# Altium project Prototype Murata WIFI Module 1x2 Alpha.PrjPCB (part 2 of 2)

## Sheet FPGA Config.SchDoc: FPGA Configuration
size B; Date: 10/29/2013; DrawnBy: David McCoy; Engineer: David McCoy (Cospan Design); DocumentNumber: 4; Revision: A; SheetNumber: 4; SheetTotal: 11
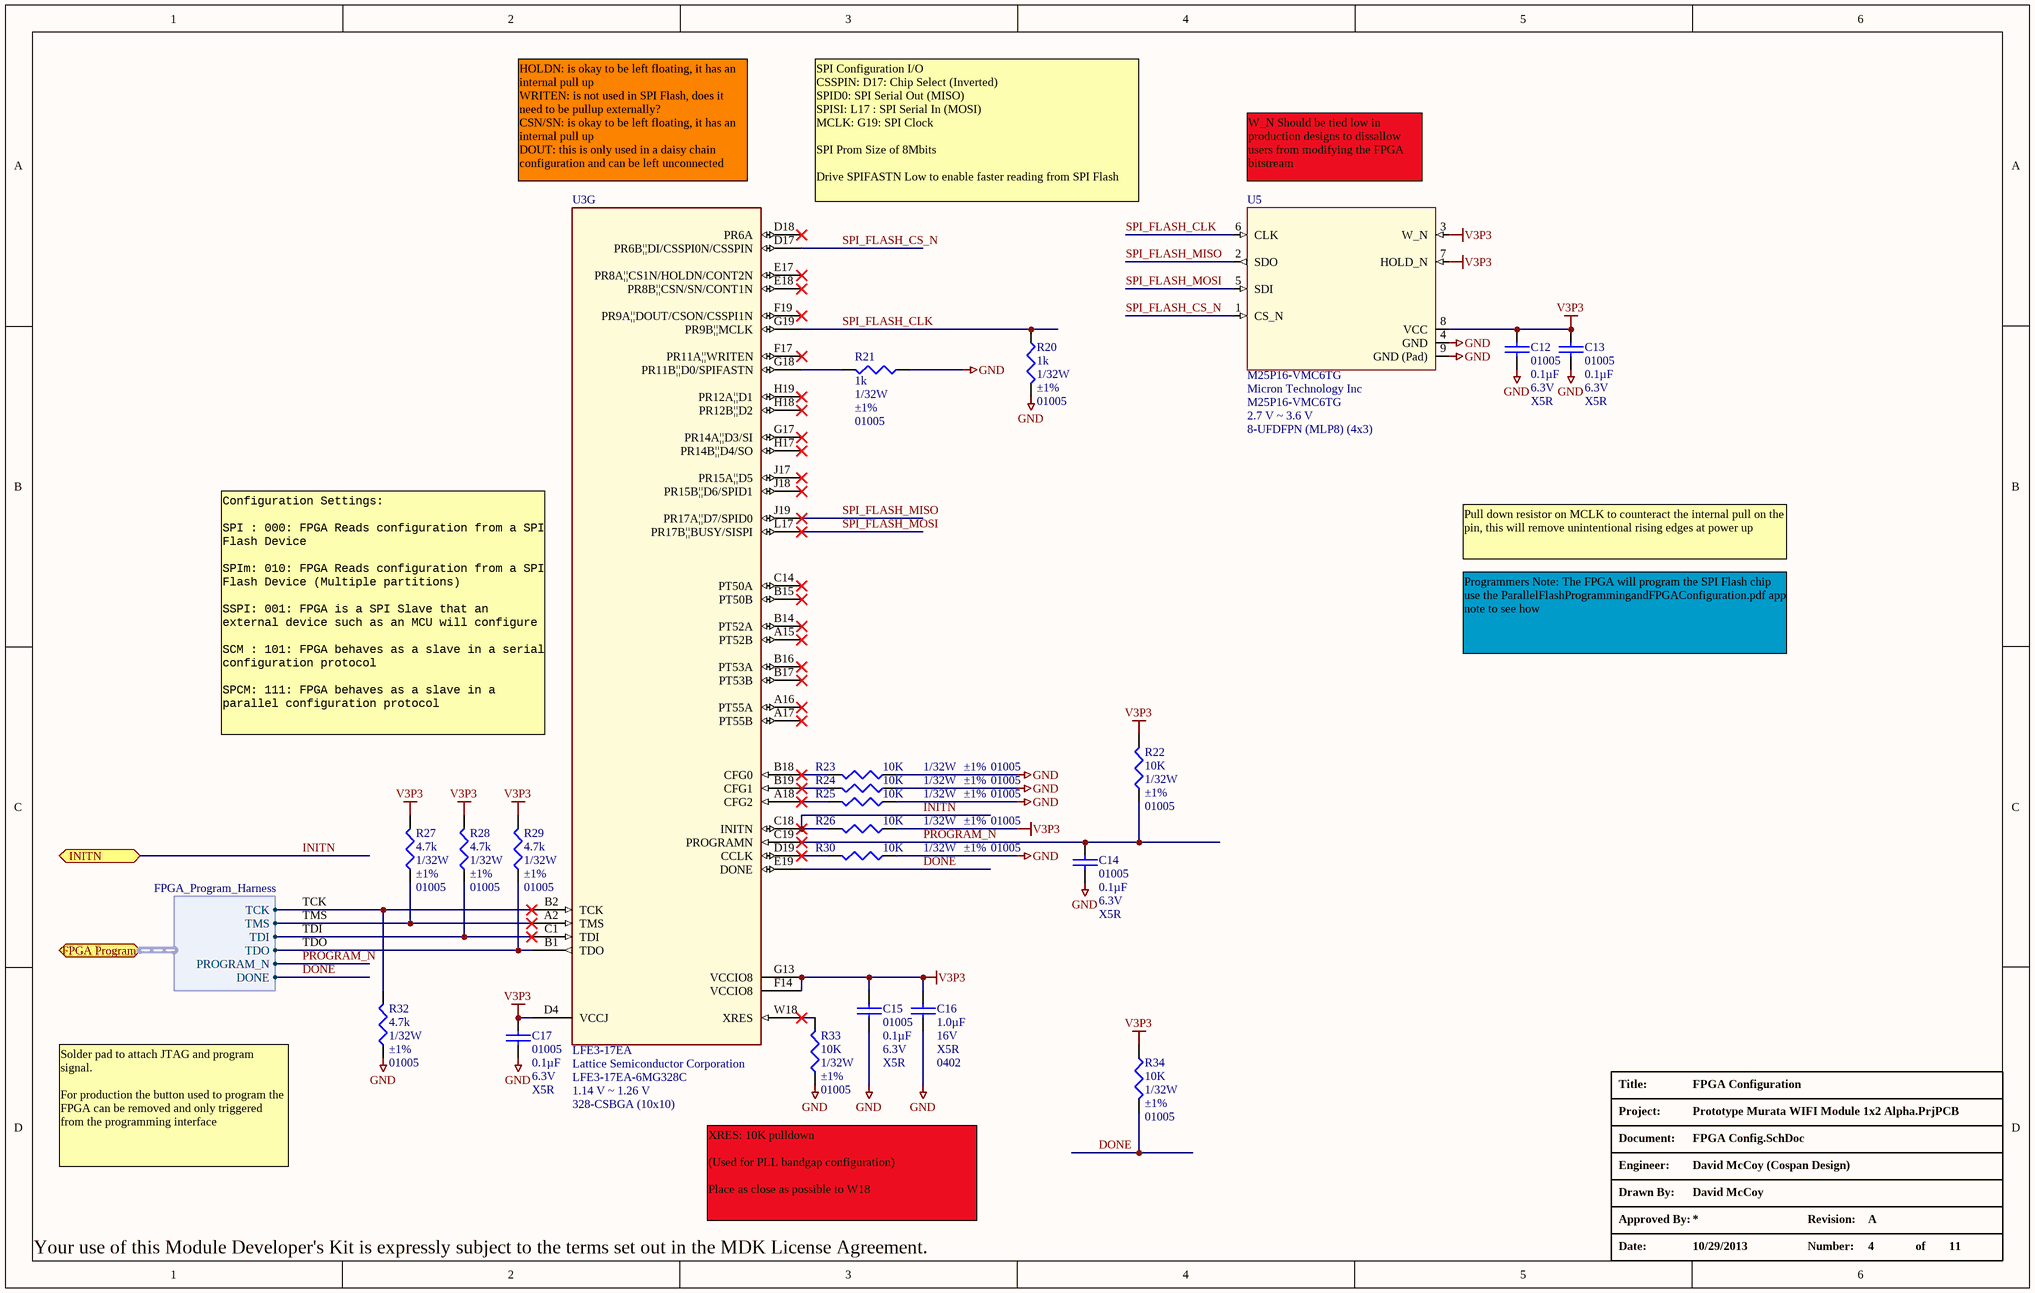
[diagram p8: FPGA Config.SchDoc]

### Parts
C12  Package / Case: 01005  Capacitance: 0.1µF  Voltage - Rated: 6.3V  Temperature Coefficient: X5R  [C_01005]  (hidden comment: 0.1uF)
C13  Package / Case: 01005  Capacitance: 0.1µF  Voltage - Rated: 6.3V  Temperature Coefficient: X5R  [C_01005]  (hidden comment: 0.1uF)
C14  Package / Case: 01005  Capacitance: 0.1µF  Voltage - Rated: 6.3V  Temperature Coefficient: X5R  [C_01005]  (hidden comment: 0.1uF)
C15  Package / Case: 01005  Capacitance: 0.1µF  Voltage - Rated: 6.3V  Temperature Coefficient: X5R  [C_01005]  (hidden comment: 0.1uF)
C16  Capacitance: 1.0µF  Voltage - Rated: 16V  Temperature Coefficient: X5R  Package / Case: 0402  [C_ERA-0402]  (hidden comment: 1.0uF)
C17  Package / Case: 01005  Capacitance: 0.1µF  Voltage - Rated: 6.3V  Temperature Coefficient: X5R  [C_01005]  (hidden comment: 0.1uF)
R20  Power (Watts): 1/32W  Tolerance: ±1%  Case: 01005  [R_01005]  (hidden comment: 1k)
R21  Power (Watts): 1/32W  Tolerance: ±1%  Case: 01005  [R_01005]  (hidden comment: 1k)
R22  Power (Watts): 1/32W  Tolerance: ±1%  Case: 01005  [R_01005]  (hidden comment: 10K)
R23  Power (Watts): 1/32W  Tolerance: ±1%  Case: 01005  [R_01005]  (hidden comment: 10K)
R24  Power (Watts): 1/32W  Tolerance: ±1%  Case: 01005  [R_01005]  (hidden comment: 10K)
R25  Power (Watts): 1/32W  Tolerance: ±1%  Case: 01005  [R_01005]  (hidden comment: 10K)
R26  Power (Watts): 1/32W  Tolerance: ±1%  Case: 01005  [R_01005]  (hidden comment: 10K)
R27  Power (Watts): 1/32W  Tolerance: ±1%  Case: 01005  [R_01005]  (hidden comment: 4.7k)
R28  Power (Watts): 1/32W  Tolerance: ±1%  Case: 01005  [R_01005]  (hidden comment: 4.7k)
R29  Power (Watts): 1/32W  Tolerance: ±1%  Case: 01005  [R_01005]  (hidden comment: 4.7k)
R30  Power (Watts): 1/32W  Tolerance: ±1%  Case: 01005  [R_01005]  (hidden comment: 10K)
R32  Power (Watts): 1/32W  Tolerance: ±1%  Case: 01005  [R_01005]  (hidden comment: 4.7k)
R33  Power (Watts): 1/32W  Tolerance: ±1%  Case: 01005  [R_01005]  (hidden comment: 10K)
R34  Power (Watts): 1/32W  Tolerance: ±1%  Case: 01005  [R_01005]  (hidden comment: 10K)
U3  LFE3-17EA  Manufacturer: Lattice Semiconductor Corporation  Manufacturer Part Number: LFE3-17EA-6MG328C  Voltage - Supply: 1.14 V ~ 1.26 V  Supplier Device Package: 328-CSBGA (10x10)  [BGA328C50P19X19_1000X1000X150]  (part G of 10)
U5  M25P16-VMC6TG  Manufacturer: Micron Technology Inc  Voltage - Supply: 2.7 V ~ 3.6 V  Supplier Device Package: 8-UFDFPN (MLP8) (4x3)  [UFDFN8]

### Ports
FPGA Program (harness FPGA_Program_Harness), INITN

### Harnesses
FPGA_Program_Harness: TCK, TMS, TDI, TDO, PROGRAM_N, DONE

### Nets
GND: C12.2 C13.2 C14.2 C15.2 C16.1 C17.2 R20.1 R21.2 R23.2 R24.2 R25.2 R30.2 R32.2 R33.2 U5.4(GND) U5.9(GND_(Pad))
V3P3: C12.1 C13.1 C15.1 C16.2 C17.1 R22.1 R26.2 R27.1 R28.1 R29.1 R34.2 U3.D4(VCCJ) U3.F14(VCCIO8) U3.G13(VCCIO8) U5.3(W_N) U5.7(HOLD_N) U5.8(VCC)
DONE: R34.1 U3.E19(DONE) ; port FPGA Program.DONE
INITN: R26.1 U3.C18(INITN) ; port INITN
PROGRAM_N: C14.1 R22.2 U3.C19(PROGRAMN) ; port FPGA Program.PROGRAM_N
SPI_FLASH_CLK: R20.2 U3.G19(PR9B¦¦MCLK) U5.6(CLK)
SPI_FLASH_CS_N: U3.D17(PR6B¦¦DI/CSSPI0N/CSSPIN) U5.1(CS_N)
SPI_FLASH_MISO: U3.J19(PR17A¦¦D7/SPID0) U5.2(SDO)
SPI_FLASH_MOSI: U3.L17(PR17B¦¦BUSY/SISPI) U5.5(SDI)
TCK: R32.1 U3.B2(TCK) ; port FPGA Program.TCK
TDI: R28.2 U3.C1(TDI) ; port FPGA Program.TDI
TDO: R29.2 U3.B1(TDO) ; port FPGA Program.TDO
TMS: R27.2 U3.A2(TMS) ; port FPGA Program.TMS
NetR21_1: R21.1 U3.G18(PR11B¦¦D0/SPIFASTN)
NetR23_1: R23.1 U3.B18(CFG0)
NetR24_1: R24.1 U3.B19(CFG1)
NetR25_1: R25.1 U3.A18(CFG2)
NetR30_1: R30.1 U3.D19(CCLK)
NetR33_1: R33.1 U3.W18(XRES)

Not connected (* = marked no-connect by the designer): U3 A15(PT52B)* A16(PT55A)* A17(PT55B)* B14(PT52A)* B15(PT50B)* B16(PT53A)* B17(PT53B)* C14(PT50A)* D18(PR6A)* E17(PR8A¦¦CS1N/HOLDN/CONT2N)* E18(PR8B¦¦CSN/SN/CONT1N)* F17(PR11A¦¦WRITEN)* F19(PR9A¦¦DOUT/CSON/CSSPI1N)* G17(PR14A¦¦D3/SI)* H17(PR14B¦¦D4/SO)* H18(PR12B¦¦D2)* H19(PR12A¦¦D1)* J17(PR15A¦¦D5)* J18(PR15B¦¦D6/SPID1)*

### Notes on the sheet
- HOLDN: is okay to be left floating, it has an internal pull up
  WRITEN: is not used in SPI Flash, does it need to be pullup externally?
  CSN/SN: is okay to be left floating, it has an internal pull up
  DOUT: this is only used in a daisy chain configuration and can be left unconnected
- SPI Configuration I/O
  CSSPIN: D17: Chip Select (Inverted)
  SPID0: SPI Serial Out (MISO)
  SPISI: L17 : SPI Serial In (MOSI)
  MCLK: G19: SPI Clock
  SPI Prom Size of 8Mbits
  Drive SPIFASTN Low to enable faster reading from SPI Flash
- W_N Should be tied low in production designs to dissallow users from modifying the FPGA bitstream
- Pull down resistor on MCLK to counteract the internal pull on the pin, this will remove unintentional rising edges at power up
- Programmers Note: The FPGA will program the SPI Flash chip use the ParallelFlashProgrammingandFPGAConfiguration.pdf app note to see how
- (near U3) Configuration Settings:
  SPI : 000: FPGA Reads configuration from a SPI Flash Device
  SPIm: 010: FPGA Reads configuration from a SPI Flash Device (Multiple partitions)
  SSPI: 001: FPGA is a SPI Slave that an external device such as an MCU will configure
  SCM : 101: FPGA behaves as a slave in a serial configuration protocol
  SPCM: 111: FPGA behaves as a slave in a parallel configuration protocol
- Solder pad to attach JTAG and program signal.
  For production the button used to program the FPGA can be removed and only triggered from the programming interface
- XRES: 10K pulldown
  (Used for PLL bandgap configuration)
  Place as close as possible to W18

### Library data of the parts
C12-C15 C17 = C_01005_0.1uF: CAP CER 0.1UF 6.3V 20% X5R 01005; Manufacturer: TDK Corporation; Manufacturer Part Number: C0402X5R0J104M020BC
C16 = C_0402_1.0UF_16V: CAP CER 1.0UF 16V X5R 0402; Manufacturer: TDK Corporation; Manufacturer Part Number: C1005X5R1C105K; Tolerance: ±10%
R20 R21 = R_01005_1k: RES 1K OHM 1/32W 1% 01005 SM; Manufacturer: Panasonic Electronic Components; Manufacturer Part Number: ERJ-XGNF1001Y; Temperature Coefficient: ±200ppm/°C
R22-R26 R30 R33 R34 = R_01005_10K: RES 10K OHM 1/32W 1% 01005; Manufacturer: Samsung Electro-Mechanics America, Inc; Manufacturer Part Number: RC0402F103CS; Temperature Coefficient: ±250ppm/°C
R27-R29 R32 = R_01005_4.7k: RES 4.7K OHM 1/32W 1% 01005 SMD; Manufacturer: Yageo; Manufacturer Part Number: RC0100FR-074K7L; Temperature Coefficient: ±250ppm/°C
U3 = U_LFE3-17EA-MG328: IC FPGA 17KLUTS 116I/O 328-BGA; SPLIT_INST: TRUE; SWAP_INFO: (S1+S2+S3+S4+S5+S6+S7+S8+S9+S10); Number of LABs/CLBs: 2125; Number of Logic Elements/Cells: 17000; Total RAM Bits: 716800; Number of I /O: 116
U5 = U_M25P16-VMC6TG: IC FLASH 16MBIT 75MHZ 8UFDFPN; Memory Type: FLASH - NOR; Memory Size: 16M (2M x 8); Interface: SPI Serial

## Sheet Power.SchDoc: Power
size B; Date: 10/29/2013; DrawnBy: David McCoy; Engineer: David McCoy (Cospan Design); DocumentNumber: 11; Revision: A; SheetNumber: 11; SheetTotal: 11
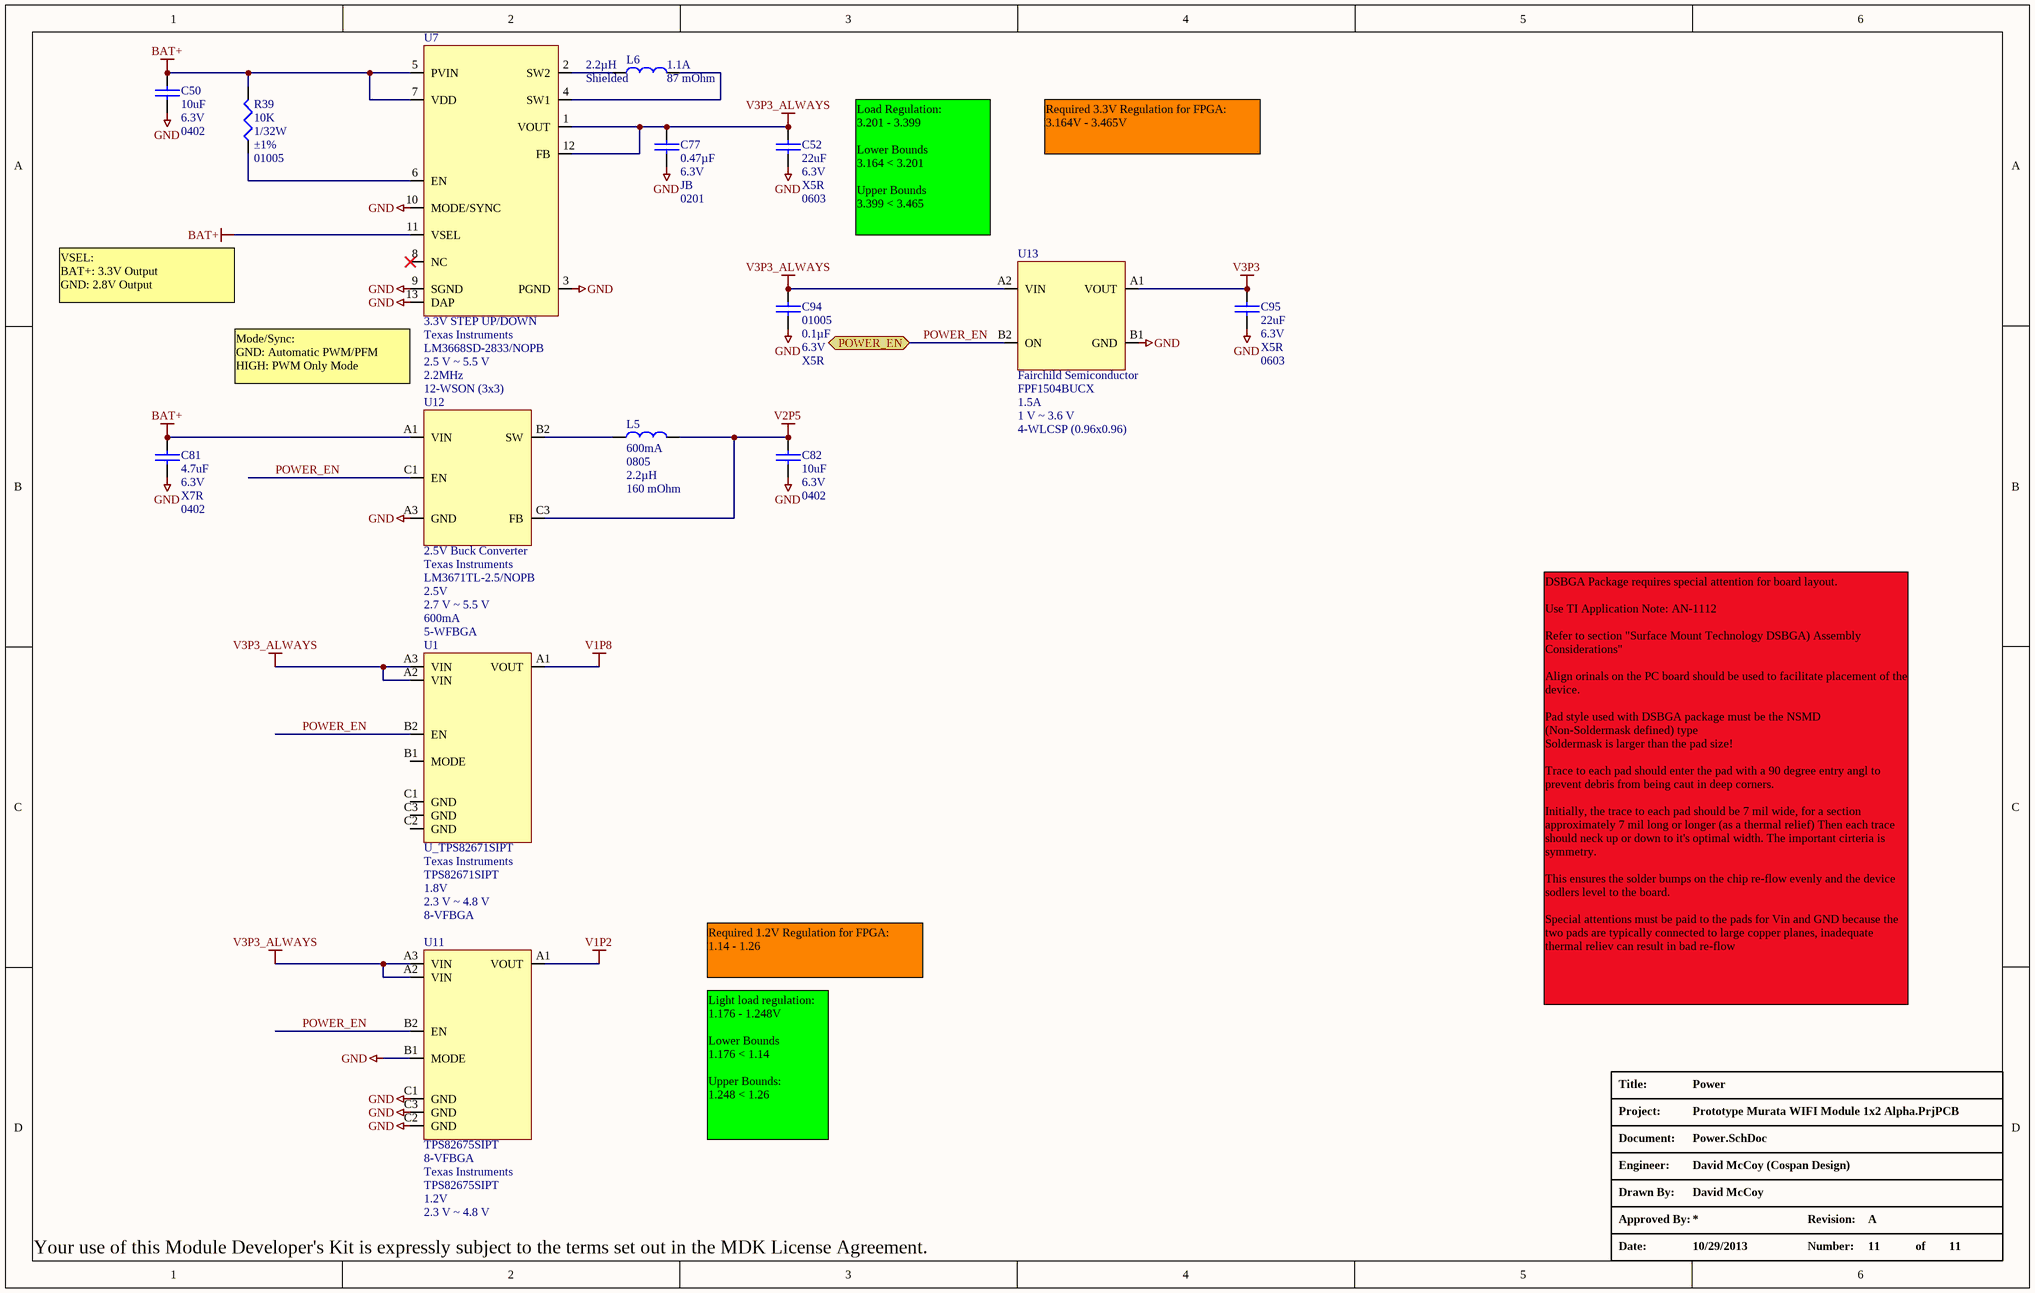
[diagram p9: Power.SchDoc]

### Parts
C50  Voltage - Rated: 6.3V  Package / Case: 0402  [C_0402]  (hidden comment: 10uF)
C52  Voltage - Rated: 6.3V  Temperature Coefficient: X5R  Package / Case: 0603  [C_ERA-0603]  (hidden comment: 22uF)
C77  Voltage - Rated: 6.3V  Temperature Coefficient: JB  Package / Case: 0201  [CAPC0201]  (hidden comment: 0.47µF)
C81  Voltage - Rated: 6.3V  Temperature Coefficient: X7R  Package / Case: 0402  [C_0402]  (hidden comment: 4.7uF)
C82  Voltage - Rated: 6.3V  Package / Case: 0402  [C_0402]  (hidden comment: 10uF)
C94  Package / Case: 01005  Capacitance: 0.1µF  Voltage - Rated: 6.3V  Temperature Coefficient: X5R  [C_01005]  (hidden comment: 0.1uF)
C95  Voltage - Rated: 6.3V  Temperature Coefficient: X5R  Package / Case: 0603  [C_ERA-0603]  (hidden comment: 22uF)
L5  Current: 600mA  Package / Case: 0805  Inductance: 2.2µH  DC Resistance (DCR): 160 mOhm  [C_ERA-0805]  (hidden comment: 2.2uH)
L6  Inductance: 2.2µH  Current - Saturation: 1.1A  Shielding: Shielded  DC Resistance (DCR): 87 mOhm  [L_SMD_2.2uH]  (hidden comment: 2.2uH Wirewound)
R39  Power (Watts): 1/32W  Tolerance: ±1%  Case: 01005  [R_01005]  (hidden comment: 10K)
U1  U_TPS82671SIPT  Manufacturer: Texas Instruments  Manufacturer Part Number: TPS82671SIPT  Voltage - Output: 1.8V  Voltage - Input: 2.3 V ~ 4.8 V  Package / Case: 8-VFBGA  [MICRP SIP]
U7  3.3V STEP UP/DOWN  Manufacturer: Texas Instruments  Manufacturer Part Number: LM3668SD-2833/NOPB  Voltage - Input: 2.5 V ~ 5.5 V  Frequency - Switching: 2.2MHz  Supplier Device Package: 12-WSON (3x3)  [QFN40P300X300X80_HS-13L]
U11  TPS82675SIPT  Package / Case: 8-VFBGA  Manufacturer: Texas Instruments  Voltage - Output: 1.2V  Voltage - Input: 2.3 V ~ 4.8 V  [MICRP SIP]
U12  2.5V Buck Converter  Manufacturer: Texas Instruments  Manufacturer Part Number: LM3671TL-2.5/NOPB  Voltage - Output: 2.5V  Voltage - Input: 2.7 V ~ 5.5 V  Current - Output: 600mA  Package / Case: 5-WFBGA  [BGA4C50P2X2_105X138X60]
U13  Manufacturer: Fairchild Semiconductor  Manufacturer Part Number: FPF1504BUCX  Current Limit: 1.5A  Voltage - Input: 1 V ~ 3.6 V  Supplier Device Package: 4-WLCSP (0.96x0.96)  [DSBGA4]  (hidden comment: Power Switch)

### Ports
POWER_EN

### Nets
BAT+: C50.2 C81.2 R39.1 U7.5(PVIN) U7.7(VDD) U7.11(VSEL) U12.A1(VIN)
GND: C50.1 C52.1 C77.1 C81.1 C82.1 C94.1 C95.1 U7.3(PGND) U7.9(SGND) U7.10(MODE/SYNC) U7.13(DAP) U11.B1(MODE) U11.C1(GND) U11.C2(GND) U11.C3(GND) U12.A3(GND) U13.B1(GND)
V1P2: U11.A1(VOUT)
V1P8: U1.A1(VOUT)
V2P5: C82.2 L5.2 U12.C3(FB)
V3P3: C95.2 U13.A1(VOUT)
V3P3_ALWAYS: C52.2 C77.2 C94.2 U1.A2(VIN) U1.A3(VIN) U7.1(VOUT) U7.12(FB) U11.A2(VIN) U11.A3(VIN) U13.A2(VIN)
POWER_EN: U1.B2(EN) U11.B2(EN) U12.C1(EN) U13.B2(ON) ; port POWER_EN
NetL5_1: L5.1 U12.B2(SW)
NetL6_1: L6.1 U7.2(SW2)
NetL6_2: L6.2 U7.4(SW1)
NetR39_2: R39.2 U7.6(EN)

Not connected (* = marked no-connect by the designer): U1 B1(MODE) C1(GND) C2(GND) C3(GND); U7 8(NC)*

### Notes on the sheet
- Required 3.3V Regulation for FPGA:
  3.164V - 3.465V
- Load Regulation:
  3.201 - 3.399
  Lower Bounds
  3.164 < 3.201
  Upper Bounds
  3.399 < 3.465
- VSEL:
  BAT+: 3.3V Output
  GND: 2.8V Output
- (near U7) Mode/Sync:
  GND: Automatic PWM/PFM
  HIGH: PWM Only Mode
- Required 1.2V Regulation for FPGA:
  1.14 - 1.26
- DSBGA Package requires special attention for board layout.
  Use TI Application Note: AN-1112
  Refer to section "Surface Mount Technology DSBGA) Assembly Considerations"
  Align orinals on the PC board should be used to facilitate placement of the device.
  Pad style used with DSBGA package must be the NSMD (Non-Soldermask defined) type
  Soldermask is larger than the pad size!
  Trace to each pad should enter the pad with a 90 degree entry angl to prevent debris from being caut in deep corners.
  Initially, the trace to each pad should be 7 mil wide, for a section approximately 7 mil long or longer (as a thermal relief) Then each trace should neck up or down to it's optimal width. The important cirteria is symmetry.
  This ensures the solder bumps on the chip re-flow evenly and the device sodlers level to the board.
  Special attentions must be paid to the pads for Vin and GND because the two pads are typically connected to large copper planes, inadequate thermal reliev can result in bad re-flow
- Light load regulation:
  1.176 - 1.248V
  Lower Bounds
  1.176 < 1.14
  Upper Bounds:
  1.248 < 1.26

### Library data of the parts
C50 C82 = C_0402_10uF: CAP CER 10UF 4V 20% X5R 0402; Manufacturer: Taiyo Yuden; Manufacturer Part Number: AMK105CBJ106MV-F
C52 C95 = C_0603_22uF: CAP CER 22UF 6.3V 20% X5R 0603; Manufacturer: TDK Corporation; Manufacturer Part Number: C1608X5R0J226M080AC
C77 = C_0201_0.47µF: CAP CER 0.47UF 6.3V 20% JB 0201; Manufacturer: TDK Corporation; Manufacturer Part Number: C0603JB0J474M030BC
C81 = C_0402_4.7uF: CAP CER 4.7UF 6.3V 10% X7R 0603; Manufacturer: Samsung Electro-Mechanics America, Inc; Manufacturer Part Number: CL10B475KQ8NQNC
C94 = C_01005_0.1uF: as C12-C15 on sheet FPGA Config
L5 = L_0805_2.2uH_160mOhm: INDUCTOR MULTILAYER 2.2UH 0805; Manufacturer: TDK Corporation; Manufacturer Part Number: MLZ2012M2R2H; Material - Core: Ferrite; Tolerance: ±20%; Current - Saturation: 400mA; Shielding: Shielded; Frequency - Self Resonant: 100MHz; Frequency - Test: 2MHz
L6 = L_SMD_2.2uH: COIL CHOKE 2.2UH SHIELDED SMD; Manufacturer: Panasonic Electronic Components; Manufacturer Part Number: ELL-VFG2R2NC; Tolerance: ±30%; Current Rating: 1.4A; Frequency - Test: 100kHz
R39 = R_01005_10K: as R22-R26 on sheet FPGA Config
U1 = U_TPS82671SIPT: IC REG BUCK SYNC 1.8V 0.6A 8USIP; Output Type: Fixed; Number of Outputs: 1; PWM Type: Voltage Mode; Frequency - Switching: 5.45MHz; Current - Output: 600mA; Synchronous Rectifier: Yes
U7 = U_LM3668SD-2833/NOPB: IC REG BUCK BST SYNC ADJ 12-LLP; Output Type: Adjustable; Number of Outputs: 1; Voltage - Output: 2.8 V ~ 3.3 V; PWM Type: Voltage Mode; Current - Output: 1A; Synchronous Rectifier: Yes
U11 = U_TPS82675SIPT: IC REG BUCK SYNC 1.2V 0.6A 8USIP; Output Type: Fixed; Number of Outputs: 1; PWM Type: Voltage Mode; Frequency - Switching: 5.45MHz; Current - Output: 600mA; Synchronous Rectifier: Yes
U12 = U_LM3671TL-2.5/NOPB: IC REG BUCK SYNC 2.5V 0.6A 5USMD; Output Type: Fixed; Number of Outputs: 1; PWM Type: Voltage Mode; Frequency - Switching: 2MHz; Synchronous Rectifier: Yes
U13 = U_FPF1504BUCX: IC LOAD MGMT SWITCH ADV 4WLCSP; Number of Outputs: 1; Rds (On): 15 mOhm; Internal Switch(s): Yes

## Sheet WIFI Module.SchDoc: WIFI Module
size B; Date: 3/12/2014; DrawnBy: David McCoy; Engineer: David McCoy (Cospan Design); DocumentNumber: 8; Revision: A; SheetNumber: 8; SheetTotal: 11
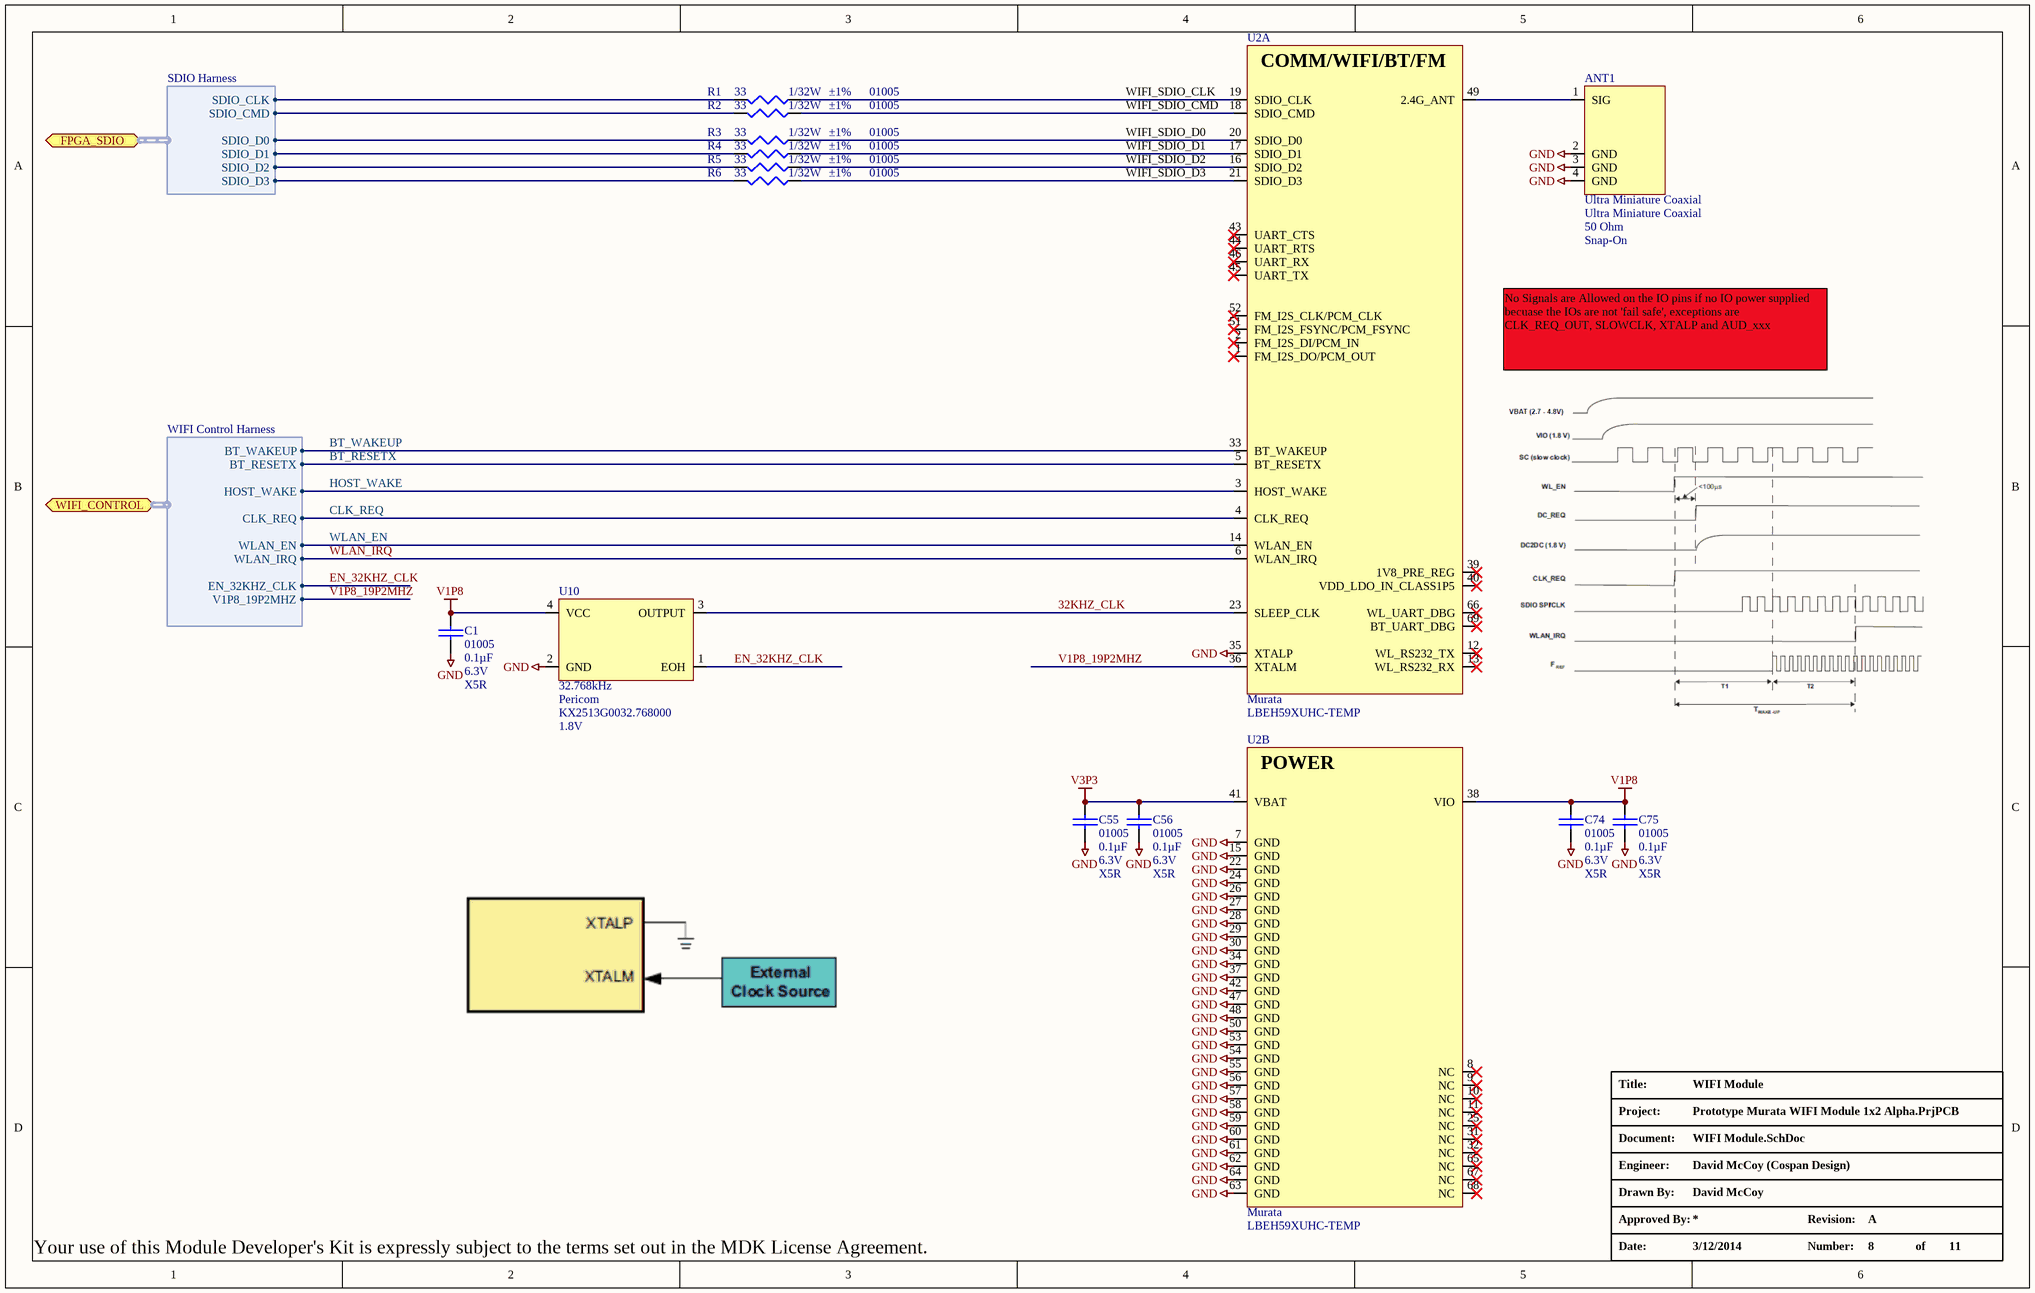
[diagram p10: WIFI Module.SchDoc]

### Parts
ANT1  Ultra Miniature Coaxial  Impedance: 50 Ohm  Fastening Type: Snap-On  [W.FL2-R-SMT-1]
C1  Package / Case: 01005  Capacitance: 0.1µF  Voltage - Rated: 6.3V  Temperature Coefficient: X5R  [C_01005]  (hidden comment: 0.1uF)
C55  Package / Case: 01005  Capacitance: 0.1µF  Voltage - Rated: 6.3V  Temperature Coefficient: X5R  [C_01005]  (hidden comment: 0.1uF)
C56  Package / Case: 01005  Capacitance: 0.1µF  Voltage - Rated: 6.3V  Temperature Coefficient: X5R  [C_01005]  (hidden comment: 0.1uF)
C74  Package / Case: 01005  Capacitance: 0.1µF  Voltage - Rated: 6.3V  Temperature Coefficient: X5R  [C_01005]  (hidden comment: 0.1uF)
C75  Package / Case: 01005  Capacitance: 0.1µF  Voltage - Rated: 6.3V  Temperature Coefficient: X5R  [C_01005]  (hidden comment: 0.1uF)
R1  Power (Watts): 1/32W  Tolerance: ±1%  Case: 01005  [R_01005]  (hidden comment: 33)
R2  Power (Watts): 1/32W  Tolerance: ±1%  Case: 01005  [R_01005]  (hidden comment: 33)
R3  Power (Watts): 1/32W  Tolerance: ±1%  Case: 01005  [R_01005]  (hidden comment: 33)
R4  Power (Watts): 1/32W  Tolerance: ±1%  Case: 01005  [R_01005]  (hidden comment: 33)
R5  Power (Watts): 1/32W  Tolerance: ±1%  Case: 01005  [R_01005]  (hidden comment: 33)
R6  Power (Watts): 1/32W  Tolerance: ±1%  Case: 01005  [R_01005]  (hidden comment: 33)
U2  Manufacturer: Murata  Manufacturer Part Number: LBEH59XUHC-TEMP  [SP-9XUH-D]  (hidden comment: MURATA WIFI Module)  (parts A,B of 2)
U10  Frequency: 32.768kHz  Manufacturer: Pericom  Voltage - Supply: 1.8V  [KX2513G0032.768000]  (hidden comment: 32.768KHz Oscillator)

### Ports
FPGA_SDIO (harness SDIO Harness), WIFI_CONTROL (harness WIFI Control Harness)

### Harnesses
SDIO Harness: SDIO_CLK, SDIO_CMD, SDIO_D3, SDIO_D2, SDIO_D1, SDIO_D0
WIFI Control Harness: BT_WAKEUP, BT_RESETX, HOST_WAKE, CLK_REQ, WLAN_EN, WLAN_IRQ, EN_32KHZ_CLK, V1P8_19P2MHZ

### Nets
GND: ANT1.2(GND) ANT1.3(GND) ANT1.4(GND) C1.1 C55.1 C56.1 C74.1 C75.1 U2.7(GND) U2.15(GND) U2.22(GND) U2.24(GND) U2.26(GND) U2.27(GND) U2.28(GND) U2.29(GND) U2.30(GND) U2.34(GND) U2.35(XTALP) U2.37(GND) U2.42(GND) U2.47(GND) U2.48(GND) U2.50(GND) U2.53(GND) U2.54(GND) U2.55(GND) U2.56(GND) U2.57(GND) U2.58(GND) U2.59(GND) U2.60(GND) U2.61(GND) U2.62(GND) U2.63(GND) U2.64(GND) U10.2(GND)
V1P8: C1.2 C74.2 C75.2 U2.38(VIO) U10.4(VCC)
V3P3: C55.2 C56.2 U2.41(VBAT)
32KHZ_CLK: U2.23(SLEEP_CLK) U10.3(OUTPUT)
BT_RESETX: U2.5(BT_RESETX) ; port WIFI_CONTROL.BT_RESETX
BT_WAKEUP: U2.33(BT_WAKEUP) ; port WIFI_CONTROL.BT_WAKEUP
CLK_REQ: U2.4(CLK_REQ) ; port WIFI_CONTROL.CLK_REQ
EN_32KHZ_CLK: U10.1(EOH) ; port WIFI_CONTROL.EN_32KHZ_CLK
HOST_WAKE: U2.3(HOST_WAKE) ; port WIFI_CONTROL.HOST_WAKE
SDIO_CLK: R1.1 ; port FPGA_SDIO.SDIO_CLK
SDIO_CMD: R2.1 ; port FPGA_SDIO.SDIO_CMD
SDIO_D0: R3.1 ; port FPGA_SDIO.SDIO_D0
SDIO_D1: R4.1 ; port FPGA_SDIO.SDIO_D1
SDIO_D2: R5.1 ; port FPGA_SDIO.SDIO_D2
SDIO_D3: R6.1 ; port FPGA_SDIO.SDIO_D3
V1P8_19P2MHZ: U2.36(XTALM) ; port WIFI_CONTROL.V1P8_19P2MHZ
WIFI_SDIO_CLK: R1.2 U2.19(SDIO_CLK)
WIFI_SDIO_CMD: R2.2 U2.18(SDIO_CMD)
WIFI_SDIO_D0: R3.2 U2.20(SDIO_D0)
WIFI_SDIO_D1: R4.2 U2.17(SDIO_D1)
WIFI_SDIO_D2: R5.2 U2.16(SDIO_D2)
WIFI_SDIO_D3: R6.2 U2.21(SDIO_D3)
WLAN_EN: U2.14(WLAN_EN) ; port WIFI_CONTROL.WLAN_EN
WLAN_IRQ: U2.6(WLAN_IRQ) ; port WIFI_CONTROL.WLAN_IRQ
NetANT1_1: ANT1.1(SIG) U2.49(2.4G_ANT)

Not connected (* = marked no-connect by the designer): U2 1(FM_I2S_DO/PCM_OUT)* 2(FM_I2S_DI/PCM_IN)* 8(NC)* 9(NC)* 10(NC)* 11(NC)* 12(WL_RS232_TX)* 13(WL_RS232_RX)* 25(NC)* 31(NC)* 32(NC)* 39(1V8_PRE_REG)* 40(VDD_LDO_IN_CLASS1P5)* 43(UART_CTS)* 44(UART_RTS)* 45(UART_TX)* 46(UART_RX)* 51(FM_I2S_FSYNC/PCM_FSYNC)* 52(FM_I2S_CLK/PCM_CLK)* 65(NC)* 66(WL_UART_DBG)* 67(NC)* 68(NC)* 69(BT_UART_DBG)*

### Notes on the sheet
- (near U2) No Signals are Allowed on the IO pins if no IO power supplied becuase the IOs are not 'fail safe', exceptions are CLK_REQ_OUT, SLOWCLK, XTALP and AUD_xxx

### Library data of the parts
ANT1 = ANT_W.FL2-R-SMT-1(40): CONN W.FL JACK STR 50 OHM SMD; Manufacturer: Hirose Electric Co Ltd; Connector Type: Jack, Male Pin; Contact Termination: Solder; Frequency - Max: 6GHz; Body Material: Phosphor Bronze; Body Finish: Silver; Center Contact Material: Brass; Center Contact Plating: Gold; Dielectric Material: Liquid Crystal Polymer (LCP)
C1 C55 C56 C74 C75 = C_01005_0.1uF: as C12-C15 on sheet FPGA Config
R1-R6 = R_01005_33: RES 33 OHM 1/32W 1% 01005; Manufacturer: Samsung Electro-Mechanics America, Inc; Manufacturer Part Number: RC0402F330CS; Temperature Coefficient: ±300ppm/°C
U2 = U_MURATA_WIFI: Embedded Solutions>Wireless Modules>Wireless LAN (WIFI)
U10 = U_KX2513G0032.768000: OSC XO 32.768KHZ SMD; Function: Tri-State (Output Enable); Output: LVCMOS, LVTTL; Frequency Stability: ±25ppm; Current - Supply (Max): 10µA

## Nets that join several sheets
BAT+: Host Comm (J3.1 TVS7.1), Power (7 pins)
GND: Block Diagram (S1.S T1.1), EPM (45 pins), Host Comm (21 pins), FPGA Banks (25 pins), FPGA Power (148 pins), FPGA Config (16 pins), Power (17 pins), WIFI Module (37 pins)
V1P2: FPGA Power (38 pins), Power (U11.A1)
V1P8: FPGA Banks (6 pins), Power (U1.A1), WIFI Module (5 pins)
V2P5: FPGA Banks (7 pins), Power (C82.2 L5.2 U12.C3)
V3P3: Block Diagram (T1.2), EPM (C2.2 L1.1 U4.4), FPGA Banks (32 pins), FPGA Power (11 pins), FPGA Config (17 pins), Power (C95.2 U13.A1), WIFI Module (C55.2 C56.2 U2.41)
V3P3_ALWAYS: Host Comm (5 pins), Power (10 pins)
BT_RESETX: FPGA Banks (U3.B6), WIFI Module (U2.5)
BT_WAKEUP: FPGA Banks (U3.C6), WIFI Module (U2.33)
C_RX_CLK_N: Host Comm (J3.6 R65.1 R67.1 TVS9.1), FPGA Banks (C54.1)
C_RX_CLK_P: Host Comm (J3.8 R66.1 R68.1 TVS8.1), FPGA Banks (C53.1)
C_RX_N: Host Comm (J3.2 TVS6.1), FPGA Banks (C49.1)
C_RX_P: Host Comm (J3.4 TVS5.1), FPGA Banks (C48.1)
C_TX_CLK_N: Host Comm (J3.7 R15.1 R37.1 TVS4.1), FPGA Banks (C47.1)
C_TX_CLK_P: Host Comm (J3.9 R36.1 R62.1 TVS3.1), FPGA Banks (C46.1)
C_TX_N: Host Comm (J3.3 TVS2.1), FPGA Banks (C45.1)
C_TX_P: Host Comm (J3.5 TVS1.1), FPGA Banks (C43.1)
CLK_REQ: FPGA Banks (U3.A7), WIFI Module (U2.4)
DETECT_RX: Host Comm (R69.2), FPGA Banks (U3.R19)
EN_32KHZ_CLK: FPGA Banks (U3.C8), WIFI Module (U10.1)
EPM_HBA_N: EPM (Q3.1), FPGA Banks (U3.T3)
EPM_HBA_P: EPM (Q2.1 R12.1), FPGA Banks (U3.U1)
EPM_HBB_N: EPM (Q8.1), FPGA Banks (U3.U2)
EPM_HBB_P: EPM (Q7.1 R41.1), FPGA Banks (U3.T2)
EPM_HBC_N: EPM (Q10.1), FPGA Banks (U3.T1)
EPM_HBC_P: EPM (Q9.1 R42.1), FPGA Banks (U3.R1)
EPM_HBD_N: EPM (Q12.1), FPGA Banks (U3.R3)
EPM_HBD_P: EPM (Q11.1 R44.1), FPGA Banks (U3.R2)
EPM_HBE_N: EPM (Q19.1), FPGA Banks (U3.W2)
EPM_HBE_P: EPM (Q18.1 R59.1), FPGA Banks (U3.V1)
EPM_HBF_N: EPM (Q21.1), FPGA Banks (U3.R17)
EPM_HBF_P: EPM (Q20.1 R60.1), FPGA Banks (U3.R18)
EPM_HBG_N: EPM (Q23.1), FPGA Banks (U3.T18)
EPM_HBG_P: EPM (Q22.1 R61.1), FPGA Banks (U3.T17)
EPM_REG_EN: EPM (R16.1 U4.6), FPGA Banks (U3.V2)
HOST_WAKE: FPGA Banks (U3.A6), WIFI Module (U2.3)
POWER_EN: Host Comm (D3.2 D4.2 R47.1), Power (U1.B2 U11.B2 U12.C1 U13.B2)
POWER_HOLD: Host Comm (D4.1 R10.2), FPGA Banks (U3.P17)
SDIO_CLK: FPGA Banks (U3.A3), WIFI Module (R1.1)
SDIO_CMD: FPGA Banks (U3.B3), WIFI Module (R2.1)
SDIO_D0: FPGA Banks (U3.A4), WIFI Module (R3.1)
SDIO_D1: FPGA Banks (U3.B4), WIFI Module (R4.1)
SDIO_D2: FPGA Banks (U3.A5), WIFI Module (R5.1)
SDIO_D3: FPGA Banks (U3.B5), WIFI Module (R6.1)
V1P8_19P2MHZ: FPGA Banks (U3.B8), WIFI Module (U2.36)
WAKE_RX: Host Comm (R64.2), FPGA Banks (U3.U18)
WAKE_TX: Host Comm (R36.2 R63.2), FPGA Banks (U3.T19)
WLAN_EN: FPGA Banks (U3.C7), WIFI Module (U2.14)
WLAN_IRQ: FPGA Banks (U3.B7), WIFI Module (U2.6)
